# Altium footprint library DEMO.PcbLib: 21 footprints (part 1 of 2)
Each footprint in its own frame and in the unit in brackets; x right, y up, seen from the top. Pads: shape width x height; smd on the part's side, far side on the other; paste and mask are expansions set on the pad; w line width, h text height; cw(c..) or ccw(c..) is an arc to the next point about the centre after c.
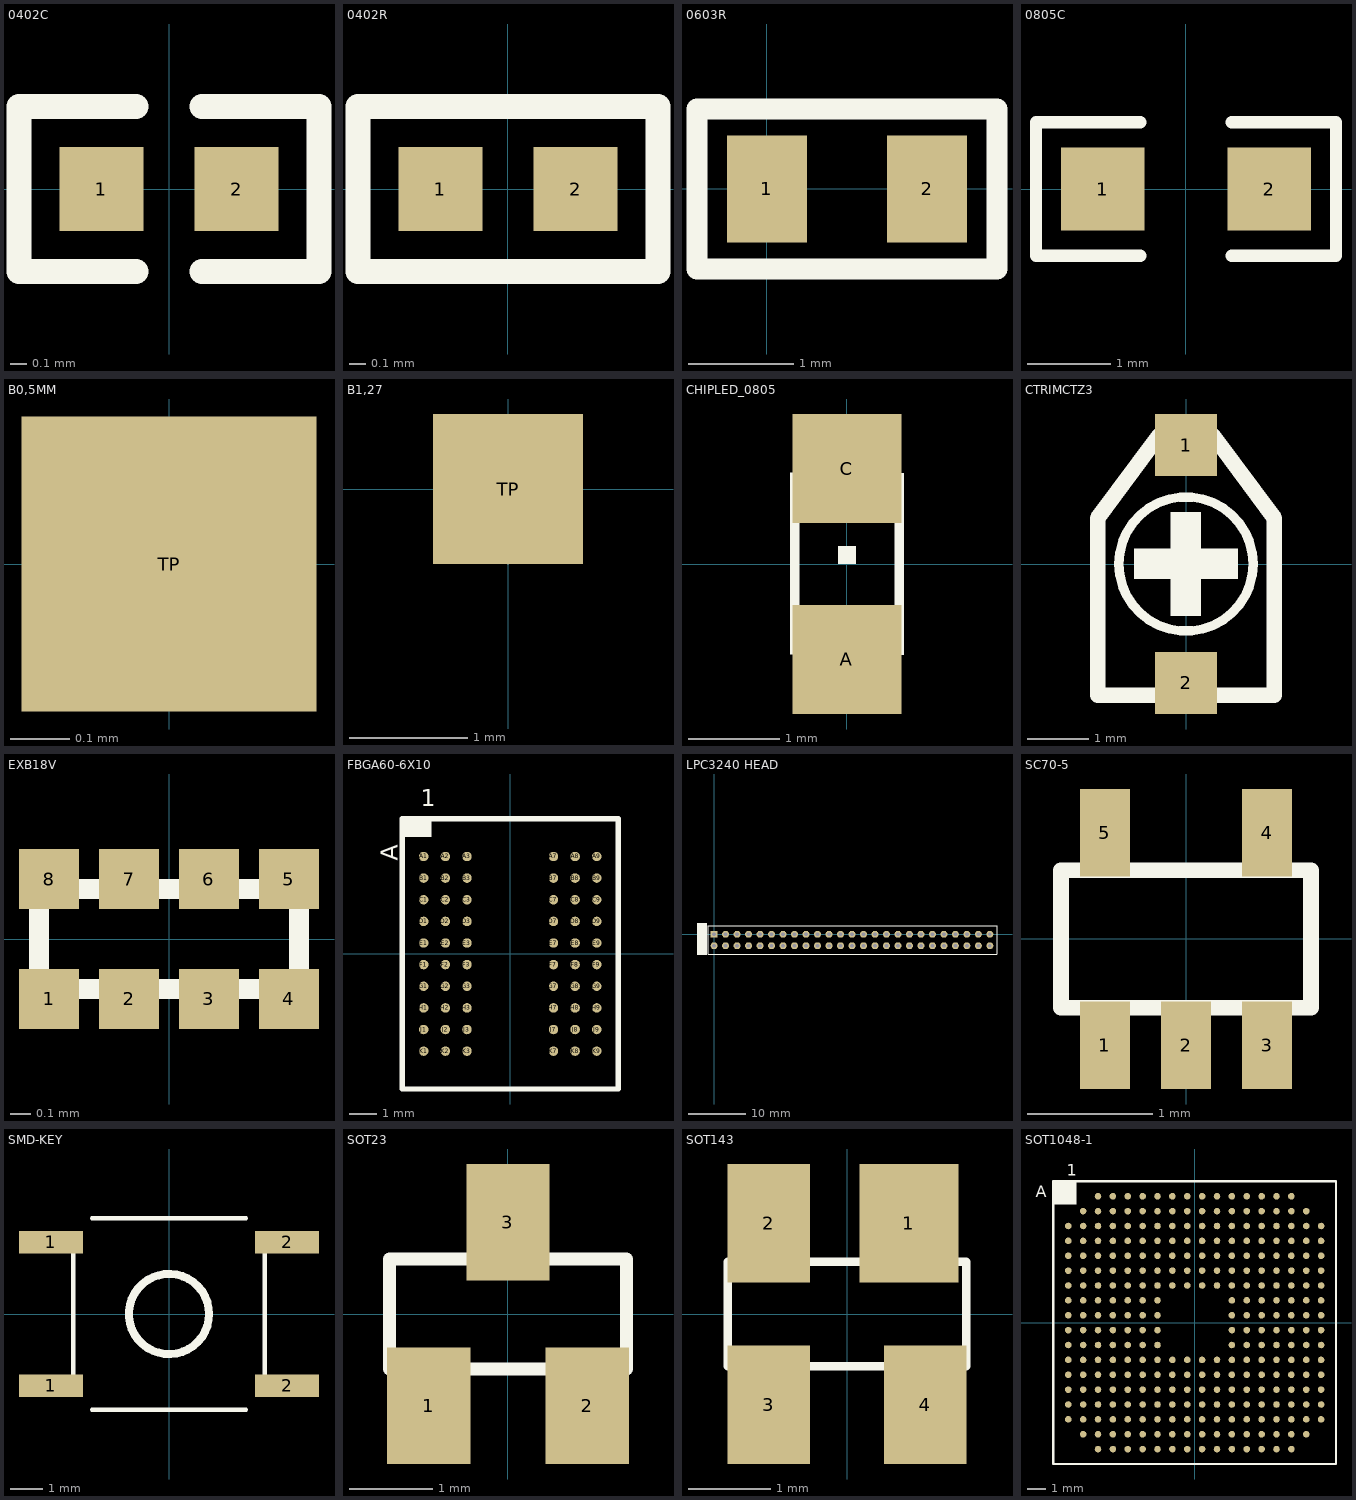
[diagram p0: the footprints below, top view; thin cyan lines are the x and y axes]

## 0402C [mm]
pads (2):
  rect 0.51x0.51 smd: 1(-0.41,0) 2(0.41,0)
Top Overlay:
  lines w0.15: -0.2,-0.5 -0.91,-0.5 -0.91,0.5 -0.2,0.5 ; 0.2,-0.5 0.91,-0.5 0.91,0.5 0.2,0.5

## 0402R [mm]
pads (2):
  rect 0.51x0.51 smd: 1(-0.41,0) 2(0.41,0)
Top Overlay:
  lines w0.15: -0.91,-0.5 -0.91,0.5 0.91,0.5 0.91,-0.5 -0.91,-0.5

## 0603R [mil]
pads (2):
  rect 30x40 smd: 1(0.01,0.01) 2(60.01,0.01)
Top Overlay:
  lines w7.87: 86.15,-30.03 86.15,30.01 -26.13,30.01 -26.13,-29.99 86.15,-29.99

## 0805C [mm]
pads (2):
  rect 1x1 smd: 1(-1,0) 2(1,0)
Top Overlay:
  lines w0.15: -0.55,-0.8 -1.8,-0.8 -1.8,0.8 -0.55,0.8 ; 0.55,-0.8 1.8,-0.8 1.8,0.8 0.55,0.8

## B0,5MM [mm]
height 3
pads (1):
  rect 0.5x0.5 smd: TP(0,0)

## B1,27 [mm]
height 3
pads (1):
  rect 1.27x1.27 smd: TP(0,0)
Top Overlay:
  lines w0.002: -0.635,0 0.635,0 ; 0,-0.635 0,0.635

## CHIPLED_0805 [mm]
height 3
pads (2):
  rect 1.2x1.2 smd: A(0,-1.05) C(0,1.05)
Top Overlay:
  circle w0.102: c-0.45,0.85 r0.103
  rectangle: 0.3,0.5 0.625,1
  rectangle: -0.325,0.5 -0.175,0.75
  rectangle: 0.175,0.5 0.325,0.75
  rectangle: -0.2,0.5 0.2,0.675
  rectangle: 0.3,-1 0.625,-0.5
  rectangle: -0.625,-0.994 -0.3,-0.494
  rectangle: 0.175,-0.75 0.325,-0.5
  rectangle: -0.325,-0.75 -0.175,-0.5
  rectangle: -0.2,-0.675 0.2,-0.5
  rectangle: -0.1,0 0.1,0.2
  rectangle: -0.6,0.506 -0.3,0.806
  rectangle: -0.625,0.931 -0.3,1.006
  lines w0.102: -0.575,-0.5 -0.575,0.925 ; -0.35,-0.925 cw(c0,-0.979) 0.35,-0.925 ; -0.35,0.925 ccw(c0,0.979) 0.35,0.925 ; 0.575,-0.525 0.575,0.525

## CTRIMCTZ3 [mil]
height 118.11
pads (2):
  rect 40x40 smd: 1(0,76.77) 2(0,-76.77)
Top Overlay:
  circle w6: c0,0 r43.31
  rectangle: -33.47,-9.84 33.47,9.85
  rectangle: -9.85,-33.47 9.84,33.47
  lines w10: -23.62,-84.64 -57.09,-84.64 ; 23.62,-84.64 57.09,-84.64 ; -57.09,-84.64 -57.09,29.53 ; -57.09,-84.64 57.09,-84.64 ; -57.09,-84.64 -57.09,29.53 ; -57.09,29.53 -17.72,82.68 ; -57.09,29.53 -17.72,82.68 ; -17.72,82.68 17.72,82.68 ; 17.72,82.68 57.09,29.53 ; 17.72,82.68 57.09,29.53 ; 57.09,-84.64 57.09,29.53 ; 57.09,-84.64 57.09,29.53

## EXB18V [mm]
height 3
pads (8):
  rect 0.3x0.3 smd: 1(-0.6,-0.3) 2(-0.2,-0.3) 3(0.2,-0.3) 4(0.6,-0.3) 5(0.6,0.3) 6(0.2,0.3) 7(-0.2,0.3) 8(-0.6,0.3)
Top Overlay:
  lines w0.102: -0.65,-0.05 -0.65,0.05 ; 0.65,-0.05 0.65,0.05 ; -0.65,-0.25 -0.65,0.25 0.65,0.25 0.65,-0.25 -0.65,-0.25

## FBGA60-6X10 [mm]
pads (60):
  round 0.35 smd: A1(-3.2,3.6) A2(-2.4,3.6) A3(-1.6,3.6) A7(1.6,3.6) A8(2.4,3.6) A9(3.2,3.6) B1(-3.2,2.8) B2(-2.4,2.8) B3(-1.6,2.8) B7(1.6,2.8) B8(2.4,2.8) B9(3.2,2.8) C1(-3.2,2) C2(-2.4,2) C3(-1.6,2) C7(1.6,2) C8(2.4,2) C9(3.2,2) D1(-3.2,1.2) D2(-2.4,1.2) D3(-1.6,1.2) D7(1.6,1.2) D8(2.4,1.2) D9(3.2,1.2) E1(-3.2,0.4) E2(-2.4,0.4) E3(-1.6,0.4) E7(1.6,0.4) E8(2.4,0.4) E9(3.2,0.4) F1(-3.2,-0.4) F2(-2.4,-0.4) F3(-1.6,-0.4) F7(1.6,-0.4) F8(2.4,-0.4) F9(3.2,-0.4) G1(-3.2,-1.2) G2(-2.4,-1.2) G3(-1.6,-1.2) G7(1.6,-1.2) G8(2.4,-1.2) G9(3.2,-1.2) H1(-3.2,-2) H2(-2.4,-2) H3(-1.6,-2) H7(1.6,-2) H8(2.4,-2) H9(3.2,-2) J1(-3.2,-2.8) J2(-2.4,-2.8) J3(-1.6,-2.8) J7(1.6,-2.8) J8(2.4,-2.8) J9(3.2,-2.8) K1(-3.2,-3.6) K2(-2.4,-3.6) K3(-1.6,-3.6) K7(1.6,-3.6) K8(2.4,-3.6) K9(3.2,-3.6)
Top Overlay:
  rectangle: -4,4.318 -2.921,5
  lines w0.203: -4,-5 4,-5 4,5 -4,5 -4,-5
  text "1" at -3.302,5.461 h0.64
  text "A" at -4.165,3.446 h0.64

## LPC3240 HEAD [mm]
pads (50):
  rect 1.2x1.2 hole 0.65: 1(0,0)
  round 1.2 hole 0.65: 2(0,-2) 3(2,0) 4(2,-2) 5(4,0) 6(4,-2) 7(6,0) 8(6,-2) 9(8,0) 10(8,-2) 11(10,0) 12(10,-2) 13(12,0) 14(12,-2) 15(14,0) 16(14,-2) 17(16,0) 18(16,-2) 19(18,0) 20(18,-2) 21(20,0) 22(20,-2) 23(22,0) 24(22,-2) 25(24,0) 26(24,-2) 27(26,0) 28(26,-2) 29(28,0) 30(28,-2) 31(30,0) 32(30,-2) 33(32,0) 34(32,-2) 35(34,0) 36(34,-2) 37(36,0) 38(36,-2) 39(38,0) 40(38,-2) 41(40,0) 42(40,-2) 43(42,0) 44(42,-2) 45(44,0) 46(44,-2) 47(46,0) 48(46,-2) 49(48,0) 50(48,-2)
Top Overlay:
  rectangle: -2.975,-3.6 -1.25,1.95
  lines w0.2: 49.226,-3.5 -1,-3.5 -1,1.5 49.239,1.5 49.239,-3.487

## SC70-5 [mm]
pads (5):
  rect 0.4x0.7 smd: 1(-0.65,-0.85) 2(0,-0.85) 3(0.65,-0.85) 4(0.65,0.85) 5(-0.65,0.85)
Top Overlay:
  lines w0.127: -1,-0.55 1,-0.55 1,0.55 -1,0.55 -1,-0.55

## SMD-KEY [mm]
pads (4):
  rect 2x0.7 smd: 1(-3.7,-2.25) 1(-3.7,2.25) 2(3.7,-2.25) 2(3.7,2.25)
Top Overlay:
  circle w0.254: c0,0 r1.257
  lines w0.127: -3,-2.413 -3,0 -3,2.413 ; -2.413,-3 0,-3 2.413,-3 ; -2.413,3 0,3 2.413,3 ; 3,-2.413 3,0 3,2.413

## SOT23 [mm]
pads (3):
  rect 1x1.4 smd: 1(-0.95,-1.1) 2(0.95,-1.1) 3(0,1.1)
Top Overlay:
  lines w0.152: -1.422,-0.152 -1.422,0.66 ; -0.864,0.66 -1.422,0.66 ; 0.864,0.66 1.422,0.66 ; 1.422,-0.152 1.422,0.66 ; -1.422,0.66 1.422,0.66 ; -1.422,0.66 -1.422,-0.66 1.422,-0.66 1.422,0.66

## SOT143 [mm]
pads (4):
  rect 1.2x1.44 smd: 1(0.75,1.1)
  rect 1x1.44 smd: 2(-0.95,1.1) 3(-0.95,-1.1) 4(0.95,-1.1)
Top Overlay:
  lines w0.1: -1.448,-0.635 1.448,-0.635 1.448,0.635 -1.448,0.635 -1.448,-0.635

## SOT1048-1 [mm]
pads (296):
  round 0.35 smd: A3(-5.184,6.78) A4(-4.387,6.78) A5(-3.589,6.78) A6(-2.791,6.78) A7(-1.994,6.78) A8(-1.196,6.78) A9(-0.399,6.78) A10(0.399,6.78) A11(1.196,6.78) A12(1.994,6.78) A13(2.791,6.78) A14(3.589,6.78) A15(4.387,6.78) A16(5.184,6.78) B2(-5.982,5.982) B3(-5.184,5.982) B4(-4.387,5.982) B5(-3.589,5.982) B6(-2.791,5.982) B7(-1.994,5.982) B8(-1.196,5.982) B9(-0.399,5.982) B10(0.399,5.982) B11(1.196,5.982) B12(1.994,5.982) B13(2.791,5.982) B14(3.589,5.982) B15(4.387,5.982) B16(5.184,5.982) B17(5.982,5.982) C1(-6.779,5.184) C2(-5.982,5.184) C3(-5.184,5.184) C4(-4.387,5.184) C5(-3.589,5.184) C6(-2.791,5.184) C7(-1.994,5.184) C8(-1.196,5.184) C9(-0.399,5.184) C10(0.399,5.184) C11(1.196,5.184) C12(1.994,5.184) C13(2.791,5.184) C14(3.589,5.184) C15(4.387,5.184) C16(5.184,5.184) C17(5.982,5.184) C18(6.779,5.184) D1(-6.779,4.387) D2(-5.982,4.387) D3(-5.184,4.387) D4(-4.387,4.387) D5(-3.589,4.387) D6(-2.791,4.387) D7(-1.994,4.387) D8(-1.196,4.387) D9(-0.399,4.387) D10(0.399,4.387) D11(1.196,4.387) D12(1.994,4.387) D13(2.791,4.387) D14(3.589,4.387) D15(4.387,4.387) D16(5.184,4.387) D17(5.982,4.387) D18(6.779,4.387) E1(-6.779,3.589) E2(-5.982,3.589) E3(-5.184,3.589) E4(-4.387,3.589) E5(-3.589,3.589) E6(-2.791,3.589) E7(-1.994,3.589) E8(-1.196,3.589) E9(-0.399,3.589) E10(0.399,3.589) E11(1.196,3.589) E12(1.994,3.589) E13(2.791,3.589) E14(3.589,3.589) E15(4.387,3.589) E16(5.184,3.589) E17(5.982,3.589) E18(6.779,3.589) F1(-6.779,2.792) F2(-5.982,2.792) F3(-5.184,2.792) F4(-4.387,2.792) F5(-3.589,2.792) F6(-2.791,2.792) F7(-1.994,2.792) F8(-1.196,2.792) F9(-0.399,2.792) F10(0.399,2.792) F11(1.196,2.792) F12(1.994,2.792) F13(2.791,2.792) F14(3.589,2.792) F15(4.387,2.792) F16(5.184,2.792) F17(5.982,2.792) F18(6.779,2.792) G1(-6.779,1.994) G2(-5.982,1.994) G3(-5.184,1.994) G4(-4.387,1.994) G5(-3.589,1.994) G6(-2.791,1.994) G7(-1.994,1.994) G8(-1.196,1.994) G9(-0.399,1.994) G10(0.399,1.994) G11(1.196,1.994) G12(1.994,1.994) G13(2.791,1.994) G14(3.589,1.994) G15(4.387,1.994) G16(5.184,1.994) G17(5.982,1.994) G18(6.779,1.994) H1(-6.779,1.197) H2(-5.982,1.197) H3(-5.184,1.197) H4(-4.387,1.197) H5(-3.589,1.197) H6(-2.791,1.197) H7(-1.994,1.197) H12(1.994,1.197) H13(2.791,1.197) H14(3.589,1.197) H15(4.387,1.197) H16(5.184,1.197) H17(5.982,1.197) H18(6.779,1.197) J1(-6.779,0.399) J2(-5.982,0.399) J3(-5.184,0.399) J4(-4.387,0.399) J5(-3.589,0.399) J6(-2.791,0.399) J7(-1.994,0.399) J12(1.994,0.399) J13(2.791,0.399) J14(3.589,0.399) J15(4.387,0.399) J16(5.184,0.399) J17(5.982,0.399) J18(6.779,0.399) K1(-6.779,-0.399) K2(-5.982,-0.399) K3(-5.184,-0.399) K4(-4.387,-0.399) K5(-3.589,-0.399) K6(-2.791,-0.399) K7(-1.994,-0.399) K12(1.994,-0.399) K13(2.791,-0.399) K14(3.589,-0.399) K15(4.387,-0.399) K16(5.184,-0.399) K17(5.982,-0.399) K18(6.779,-0.399) L1(-6.779,-1.196) L2(-5.982,-1.196) L3(-5.184,-1.196) L4(-4.387,-1.196) L5(-3.589,-1.196) L6(-2.791,-1.196) L7(-1.994,-1.196) L12(1.994,-1.196) L13(2.791,-1.196) L14(3.589,-1.196) L15(4.387,-1.196) L16(5.184,-1.196) L17(5.982,-1.196) L18(6.779,-1.196) M1(-6.779,-1.994) M2(-5.982,-1.994) M3(-5.184,-1.994) M4(-4.387,-1.994) M5(-3.589,-1.994) M6(-2.791,-1.994) M7(-1.994,-1.994) M8(-1.196,-1.994) M9(-0.399,-1.994) M10(0.399,-1.994) M11(1.196,-1.994) M12(1.994,-1.994) M13(2.791,-1.994) M14(3.589,-1.994) M15(4.387,-1.994) M16(5.184,-1.994) M17(5.982,-1.994) M18(6.779,-1.994) N1(-6.779,-2.791) N2(-5.982,-2.791) N3(-5.184,-2.791) N4(-4.387,-2.791) N5(-3.589,-2.791) N6(-2.791,-2.791) N7(-1.994,-2.791) N8(-1.196,-2.791) N9(-0.399,-2.791) N10(0.399,-2.791) N11(1.196,-2.791) N12(1.994,-2.791) N13(2.791,-2.791) N14(3.589,-2.791) N15(4.387,-2.791) N16(5.184,-2.791) N17(5.982,-2.791) N18(6.779,-2.791) P1(-6.779,-3.589) P2(-5.982,-3.589) P3(-5.184,-3.589) P4(-4.387,-3.589) P5(-3.589,-3.589) P6(-2.791,-3.589) P7(-1.994,-3.589) P8(-1.196,-3.589) P9(-0.399,-3.589) P10(0.399,-3.589) P11(1.196,-3.589) P12(1.994,-3.589) P13(2.791,-3.589) P14(3.589,-3.589) P15(4.387,-3.589) P16(5.184,-3.589) P17(5.982,-3.589) P18(6.779,-3.589) R1(-6.779,-4.386) R2(-5.982,-4.386) R3(-5.184,-4.386) R4(-4.387,-4.386) R5(-3.589,-4.386) R6(-2.791,-4.386) R7(-1.994,-4.386) R8(-1.196,-4.386) R9(-0.399,-4.386) R10(0.399,-4.386) R11(1.196,-4.386) R12(1.994,-4.386) R13(2.791,-4.386) R14(3.589,-4.386) R15(4.387,-4.386) R16(5.184,-4.386) R17(5.982,-4.386) R18(6.779,-4.386) T1(-6.779,-5.184) T2(-5.982,-5.184) T3(-5.184,-5.184) T4(-4.387,-5.184) T5(-3.589,-5.184) T6(-2.791,-5.184) T7(-1.994,-5.184) T8(-1.196,-5.184) T9(-0.399,-5.184) T10(0.399,-5.184) T11(1.196,-5.184) T12(1.994,-5.184) T13(2.791,-5.184) T14(3.589,-5.184) T15(4.387,-5.184) T16(5.184,-5.184) T17(5.982,-5.184) T18(6.779,-5.184) U2(-5.982,-5.982) U3(-5.184,-5.982) U4(-4.387,-5.982) U5(-3.589,-5.982) U6(-2.791,-5.982) U7(-1.994,-5.982) U8(-1.196,-5.982) U9(-0.399,-5.982) U10(0.399,-5.982) U11(1.196,-5.982) U12(1.994,-5.982) U13(2.791,-5.982) U14(3.589,-5.982) U15(4.387,-5.982) U16(5.184,-5.982) U17(5.982,-5.982) V3(-5.184,-6.779) V4(-4.387,-6.779) V5(-3.589,-6.779) V6(-2.791,-6.779) V7(-1.994,-6.779) V8(-1.196,-6.779) V9(-0.399,-6.779) V10(0.399,-6.779) V11(1.196,-6.779) V12(1.994,-6.779) V13(2.791,-6.779) V14(3.589,-6.779) V15(4.387,-6.779) V16(5.184,-6.779)
Top Overlay:
  rectangle: -7.62,6.35 -6.35,7.62
  lines w0.127: -7.577,-7.577 7.577,-7.577 7.577,7.577 -7.577,7.577 -7.577,-7.577
  text "1" at -6.858,7.874 h0.64
  text "A" at -8.509,6.731 h0.64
